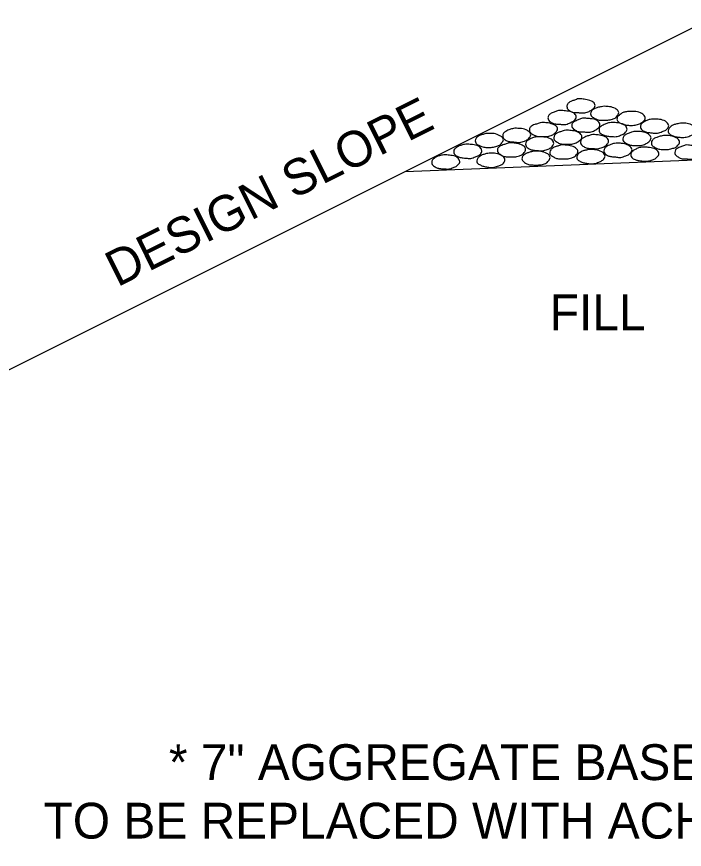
# Model space of a CAD drawing. Extents: x 3575 to 11445, y 9479 to 13278.
# Drawn here: x 4373.6 to 4485.4, y 10710.3 to 10849.7 of the extents above; entities that cross this region are included whole.
import ezdxf

# ---------------------------------------------------------------- set-up
doc = ezdxf.new("R2010")
doc.units = 0
doc.layers.add('STAMP_PE_CRAFTON-SIGNATURE', color=7, linetype='Continuous')

msp = doc.modelspace()

# ---------------------------------------------------------------- linework, layer by layer
at = {"layer": 'STAMP_PE_CRAFTON-SIGNATURE'}
for p, q in [((4366.36, 10787.63), (4490.54, 10849.68)), ((4438.69, 10823.77), (4689.85, 10833.78))]:
    msp.add_line(p, q, dxfattribs=at)
for points in [[(4468.06, 10835.92), (4468.89, 10835.82), (4469.88, 10835.55), (4470.42, 10835.1), (4470.49, 10834.8), (4470.24, 10834.3), (4469.92, 10834.07), (4469.35, 10833.75), (4468.57, 10833.56), (4468.14, 10833.56), (4467.55, 10833.62), (4466.83, 10833.66), (4466.33, 10833.87), (4465.84, 10834.33), (4465.77, 10834.64), (4465.92, 10835.11), (4466.28, 10835.4), (4466.64, 10835.57), (4467.2, 10835.76), (4467.52, 10835.9), (4468.06, 10835.92)], [(4464.9, 10833.99), (4465.75, 10833.87), (4466.71, 10833.64), (4467.25, 10833.17), (4467.33, 10832.88), (4467.06, 10832.37), (4466.75, 10832.15), (4466.19, 10831.85), (4465.39, 10831.62), (4464.99, 10831.62), (4464.37, 10831.7), (4463.67, 10831.74), (4463.15, 10831.96), (4462.68, 10832.41), (4462.6, 10832.72), (4462.76, 10833.18), (4463.14, 10833.5), (4463.49, 10833.66), (4464.04, 10833.84), (4464.37, 10833.95), (4464.9, 10833.99)], [(4472.07, 10834.67), (4472.92, 10834.61), (4473.89, 10834.29), (4474.38, 10833.86), (4474.45, 10833.61), (4474.2, 10833.06), (4473.97, 10832.8), (4473.39, 10832.51), (4472.62, 10832.36), (4472.19, 10832.33), (4471.57, 10832.34), (4470.85, 10832.46), (4470.35, 10832.7), (4469.83, 10833.09), (4469.75, 10833.42), (4469.89, 10833.86), (4470.3, 10834.22), (4470.63, 10834.38), (4471.21, 10834.54), (4471.55, 10834.61), (4472.07, 10834.67)], [(4468.92, 10832.68), (4469.75, 10832.59), (4470.75, 10832.34), (4471.23, 10831.86), (4471.31, 10831.58), (4471.06, 10831.07), (4470.76, 10830.84), (4470.24, 10830.53), (4469.45, 10830.34), (4469.02, 10830.34), (4468.39, 10830.4), (4467.69, 10830.43), (4467.18, 10830.67), (4466.68, 10831.12), (4466.59, 10831.42), (4466.74, 10831.89), (4467.13, 10832.17), (4467.5, 10832.34), (4468.06, 10832.55), (4468.39, 10832.67), (4468.92, 10832.68)], [(4476.47, 10833.82), (4477.3, 10833.79), (4478.33, 10833.47), (4478.8, 10832.98), (4478.89, 10832.7), (4478.61, 10832.18), (4478.34, 10831.96), (4477.79, 10831.71), (4476.98, 10831.49), (4476.55, 10831.45), (4475.93, 10831.51), (4475.26, 10831.62), (4474.74, 10831.83), (4474.24, 10832.23), (4474.16, 10832.54), (4474.32, 10833), (4474.7, 10833.29), (4475.04, 10833.56), (4475.6, 10833.73), (4475.95, 10833.79), (4476.47, 10833.82)], [(4480.44, 10832.53), (4481.3, 10832.48), (4482.27, 10832.17), (4482.74, 10831.71), (4482.83, 10831.41), (4482.56, 10830.91), (4482.34, 10830.69), (4481.75, 10830.43), (4480.96, 10830.17), (4480.54, 10830.17), (4479.92, 10830.23), (4479.26, 10830.31), (4478.69, 10830.5), (4478.17, 10830.95), (4478.1, 10831.25), (4478.25, 10831.72), (4478.63, 10832.01), (4479.01, 10832.23), (4479.57, 10832.44), (4479.92, 10832.5), (4480.44, 10832.53)], [(4461.82, 10831.96), (4462.65, 10831.88), (4463.62, 10831.57), (4464.13, 10831.16), (4464.2, 10830.85), (4463.93, 10830.35), (4463.64, 10830.08), (4463.13, 10829.78), (4462.33, 10829.61), (4461.92, 10829.61), (4461.28, 10829.59), (4460.58, 10829.71), (4460.05, 10829.95), (4459.55, 10830.4), (4459.5, 10830.66), (4459.64, 10831.17), (4460, 10831.45), (4460.39, 10831.62), (4460.97, 10831.8), (4461.28, 10831.91), (4461.82, 10831.96)], [(4473.47, 10831.94), (4474.29, 10831.91), (4475.31, 10831.6), (4475.78, 10831.12), (4475.85, 10830.84), (4475.6, 10830.32), (4475.36, 10830.1), (4474.77, 10829.82), (4474, 10829.59), (4473.57, 10829.59), (4472.92, 10829.63), (4472.25, 10829.75), (4471.73, 10829.93), (4471.22, 10830.37), (4471.15, 10830.69), (4471.28, 10831.16), (4471.68, 10831.44), (4472.04, 10831.63), (4472.6, 10831.86), (4472.92, 10831.93), (4473.47, 10831.94)], [(4485.07, 10831.83), (4485.91, 10831.8), (4486.87, 10831.45), (4487.35, 10831.03), (4487.43, 10830.73), (4487.2, 10830.19), (4486.92, 10829.97), (4486.38, 10829.71), (4485.57, 10829.49), (4485.15, 10829.45), (4484.54, 10829.51), (4483.84, 10829.62), (4483.3, 10829.82), (4482.8, 10830.23), (4482.72, 10830.55), (4482.88, 10831), (4483.24, 10831.33), (4483.63, 10831.55), (4484.19, 10831.72), (4484.55, 10831.8), (4485.07, 10831.83)], [(4452.74, 10830.14), (4453.58, 10830.1), (4454.55, 10829.75), (4455.06, 10829.34), (4455.14, 10829.08), (4454.85, 10828.53), (4454.61, 10828.25), (4454.03, 10828.01), (4453.27, 10827.82), (4452.86, 10827.78), (4452.2, 10827.8), (4451.49, 10827.93), (4451, 10828.16), (4450.49, 10828.56), (4450.42, 10828.87), (4450.57, 10829.34), (4450.94, 10829.68), (4451.32, 10829.84), (4451.88, 10830.02), (4452.19, 10830.1), (4452.74, 10830.14)], [(4457.34, 10830.99), (4458.19, 10830.93), (4459.16, 10830.62), (4459.65, 10830.15), (4459.71, 10829.87), (4459.46, 10829.38), (4459.2, 10829.13), (4458.65, 10828.85), (4457.86, 10828.63), (4457.43, 10828.63), (4456.81, 10828.7), (4456.14, 10828.76), (4455.6, 10828.96), (4455.08, 10829.4), (4455.02, 10829.72), (4455.15, 10830.17), (4455.53, 10830.47), (4455.9, 10830.69), (4456.49, 10830.88), (4456.81, 10830.96), (4457.34, 10830.99)], [(4465.85, 10830.67), (4466.7, 10830.59), (4467.71, 10830.29), (4468.21, 10829.84), (4468.3, 10829.56), (4468.03, 10829.04), (4467.76, 10828.83), (4467.17, 10828.49), (4466.4, 10828.32), (4465.97, 10828.32), (4465.34, 10828.33), (4464.65, 10828.41), (4464.13, 10828.67), (4463.64, 10829.08), (4463.57, 10829.42), (4463.73, 10829.87), (4464.11, 10830.17), (4464.46, 10830.34), (4464.99, 10830.5), (4465.33, 10830.62), (4465.85, 10830.67)], [(4470.39, 10829.95), (4471.22, 10829.84), (4472.19, 10829.58), (4472.68, 10829.11), (4472.75, 10828.83), (4472.5, 10828.32), (4472.25, 10828.08), (4471.68, 10827.78), (4470.9, 10827.58), (4470.47, 10827.58), (4469.85, 10827.62), (4469.14, 10827.68), (4468.6, 10827.93), (4468.12, 10828.37), (4468.05, 10828.69), (4468.18, 10829.13), (4468.56, 10829.42), (4468.94, 10829.61), (4469.53, 10829.8), (4469.85, 10829.92), (4470.39, 10829.95)], [(4477.49, 10830.48), (4478.34, 10830.4), (4479.29, 10830.1), (4479.78, 10829.65), (4479.86, 10829.39), (4479.62, 10828.84), (4479.35, 10828.61), (4478.78, 10828.3), (4477.98, 10828.11), (4477.57, 10828.11), (4476.96, 10828.13), (4476.26, 10828.21), (4475.73, 10828.47), (4475.2, 10828.88), (4475.12, 10829.24), (4475.29, 10829.68), (4475.67, 10829.98), (4476.04, 10830.14), (4476.6, 10830.32), (4476.98, 10830.44), (4477.49, 10830.48)], [(4482.25, 10829.78), (4483.07, 10829.74), (4484.07, 10829.4), (4484.56, 10828.97), (4484.63, 10828.71), (4484.38, 10828.15), (4484.13, 10827.9), (4483.54, 10827.64), (4482.77, 10827.46), (4482.36, 10827.42), (4481.72, 10827.43), (4481.01, 10827.56), (4480.51, 10827.8), (4480.01, 10828.18), (4479.92, 10828.53), (4480.07, 10828.97), (4480.44, 10829.32), (4480.83, 10829.47), (4481.38, 10829.65), (4481.71, 10829.74), (4482.25, 10829.78)], [(4449.13, 10828.32), (4449.95, 10828.27), (4450.96, 10827.98), (4451.44, 10827.48), (4451.51, 10827.22), (4451.27, 10826.68), (4451, 10826.46), (4450.45, 10826.22), (4449.66, 10825.96), (4449.23, 10825.96), (4448.59, 10826.01), (4447.9, 10826.13), (4447.38, 10826.3), (4446.88, 10826.73), (4446.81, 10827.06), (4446.95, 10827.52), (4447.35, 10827.81), (4447.72, 10828.03), (4448.27, 10828.22), (4448.59, 10828.3), (4449.13, 10828.32)], [(4456.52, 10828.56), (4457.33, 10828.47), (4458.28, 10828.16), (4458.79, 10827.73), (4458.85, 10827.44), (4458.62, 10826.94), (4458.35, 10826.66), (4457.81, 10826.38), (4456.98, 10826.22), (4456.57, 10826.22), (4455.93, 10826.23), (4455.24, 10826.29), (4454.72, 10826.54), (4454.22, 10826.99), (4454.13, 10827.31), (4454.29, 10827.77), (4454.65, 10828.05), (4455.05, 10828.21), (4455.61, 10828.39), (4455.95, 10828.51), (4456.52, 10828.56)], [(4461.18, 10829.58), (4461.99, 10829.52), (4463, 10829.24), (4463.5, 10828.75), (4463.57, 10828.47), (4463.31, 10827.97), (4463.06, 10827.73), (4462.48, 10827.46), (4461.71, 10827.23), (4461.26, 10827.23), (4460.63, 10827.27), (4459.94, 10827.37), (4459.43, 10827.56), (4458.92, 10828.01), (4458.85, 10828.32), (4459, 10828.78), (4459.38, 10829.08), (4459.75, 10829.28), (4460.31, 10829.49), (4460.63, 10829.56), (4461.18, 10829.58)], [(4474.31, 10828.5), (4475.14, 10828.44), (4476.13, 10828.11), (4476.6, 10827.67), (4476.68, 10827.37), (4476.41, 10826.88), (4476.19, 10826.64), (4475.62, 10826.39), (4474.82, 10826.13), (4474.4, 10826.13), (4473.77, 10826.21), (4473.09, 10826.28), (4472.56, 10826.46), (4472.03, 10826.92), (4471.96, 10827.23), (4472.12, 10827.68), (4472.5, 10827.99), (4472.88, 10828.18), (4473.43, 10828.39), (4473.77, 10828.47), (4474.31, 10828.5)], [(4460.56, 10827.17), (4461.39, 10827.11), (4462.41, 10826.77), (4462.88, 10826.36), (4462.94, 10826.11), (4462.7, 10825.55), (4462.46, 10825.28), (4461.86, 10824.99), (4461.09, 10824.85), (4460.67, 10824.83), (4460.05, 10824.85), (4459.33, 10824.94), (4458.83, 10825.18), (4458.32, 10825.59), (4458.24, 10825.9), (4458.4, 10826.36), (4458.77, 10826.68), (4459.15, 10826.86), (4459.68, 10827.03), (4460.03, 10827.11), (4460.56, 10827.17)], [(4465.27, 10828.21), (4466.09, 10828.11), (4467.06, 10827.82), (4467.55, 10827.38), (4467.62, 10827.11), (4467.39, 10826.6), (4467.13, 10826.33), (4466.57, 10826.03), (4465.77, 10825.86), (4465.34, 10825.86), (4464.71, 10825.87), (4464.04, 10825.95), (4463.5, 10826.22), (4462.98, 10826.63), (4462.89, 10826.97), (4463.06, 10827.4), (4463.45, 10827.72), (4463.82, 10827.89), (4464.37, 10828.05), (4464.73, 10828.16), (4465.27, 10828.21)], [(4469.78, 10827.42), (4470.59, 10827.39), (4471.6, 10827.06), (4472.07, 10826.63), (4472.16, 10826.34), (4471.91, 10825.79), (4471.63, 10825.59), (4471.11, 10825.32), (4470.3, 10825.08), (4469.86, 10825.04), (4469.23, 10825.11), (4468.56, 10825.23), (4468.01, 10825.45), (4467.5, 10825.83), (4467.42, 10826.16), (4467.59, 10826.62), (4467.97, 10826.96), (4468.34, 10827.17), (4468.9, 10827.32), (4469.24, 10827.39), (4469.78, 10827.42)], [(4478.77, 10827.82), (4479.61, 10827.78), (4480.62, 10827.48), (4481.1, 10827), (4481.18, 10826.71), (4480.92, 10826.22), (4480.68, 10825.98), (4480.1, 10825.7), (4479.32, 10825.49), (4478.89, 10825.49), (4478.25, 10825.53), (4477.56, 10825.64), (4477.06, 10825.81), (4476.53, 10826.25), (4476.47, 10826.57), (4476.61, 10827.01), (4477.01, 10827.32), (4477.36, 10827.52), (4477.91, 10827.75), (4478.25, 10827.81), (4478.77, 10827.82)], [(4486.12, 10828.18), (4486.99, 10828.09), (4487.96, 10827.84), (4488.48, 10827.36), (4488.57, 10827.1), (4488.31, 10826.57), (4488.03, 10826.34), (4487.43, 10826.03), (4486.67, 10825.83), (4486.25, 10825.83), (4485.61, 10825.89), (4484.9, 10825.92), (4484.39, 10826.19), (4483.92, 10826.62), (4483.84, 10826.94), (4483.99, 10827.38), (4484.36, 10827.69), (4484.71, 10827.86), (4485.28, 10828.05), (4485.61, 10828.18), (4486.12, 10828.18)], [(4445.43, 10826.54), (4446.31, 10826.46), (4447.27, 10826.19), (4447.74, 10825.7), (4447.83, 10825.44), (4447.57, 10824.92), (4447.33, 10824.7), (4446.76, 10824.43), (4445.97, 10824.18), (4445.54, 10824.18), (4444.91, 10824.22), (4444.24, 10824.3), (4443.72, 10824.52), (4443.2, 10824.94), (4443.12, 10825.28), (4443.28, 10825.71), (4443.64, 10826.03), (4444.01, 10826.25), (4444.59, 10826.44), (4444.91, 10826.5), (4445.43, 10826.54)], [(4453.03, 10826.82), (4453.87, 10826.79), (4454.84, 10826.44), (4455.31, 10826.01), (4455.4, 10825.71), (4455.15, 10825.18), (4454.89, 10824.94), (4454.36, 10824.7), (4453.54, 10824.48), (4453.12, 10824.43), (4452.49, 10824.51), (4451.82, 10824.63), (4451.27, 10824.85), (4450.75, 10825.23), (4450.68, 10825.55), (4450.83, 10826), (4451.22, 10826.33), (4451.59, 10826.54), (4452.14, 10826.7), (4452.51, 10826.79), (4453.03, 10826.82)]]:
    msp.add_spline(points, degree=3, dxfattribs=at)

# ---------------------------------------------------------------- texts
msp.add_text('DESIGN SLOPE', height=6, rotation=26.565, dxfattribs=at).set_placement((4390.47, 10804.35))
for s, p in [('FILL', (4462.9, 10797.19)), ('* 7" AGGREGATE BASE COURSE (CLASS 7)', (4399.1, 10721.89)), ('TO BE REPLACED WITH ACHM BINDER COURSE (1")', (4378.1, 10712.1))]:
    msp.add_text(s, height=6, dxfattribs=at).set_placement(p)

doc.saveas('drawing.dxf')
